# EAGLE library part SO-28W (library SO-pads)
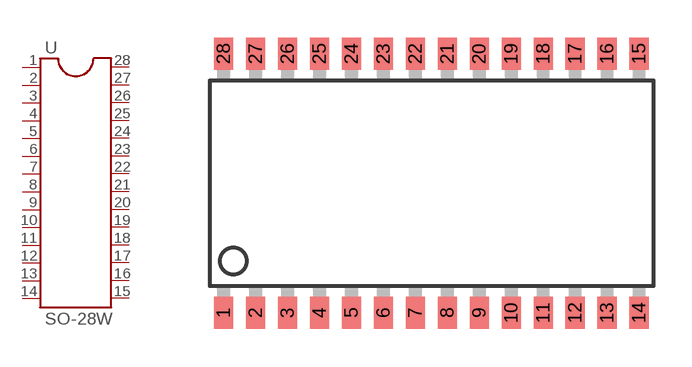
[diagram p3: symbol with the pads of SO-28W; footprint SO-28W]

Designator prefix -

## SO-28W  [SO-28W]
1  1  pas
2  2  pas
3  3  pas
4  4  pas
5  5  pas
6  6  pas
7  7  pas
8  8  pas
9  9  pas
10  10  pas
11  11  pas
12  12  pas
13  13  pas
14  14  pas
15  15  pas
16  16  pas
17  17  pas
18  18  pas
19  19  pas
20  20  pas
21  21  pas
22  22  pas
23  23  pas
24  24  pas
25  25  pas
26  26  pas
27  27  pas
28  28  pas

## Footprint SO-28W (pad centres in mm)
smd 0.762 x 1.27: 1 -7.62,-5.207; 2 -6.35,-5.207; 3 -5.08,-5.207; 4 -3.81,-5.207; 5 -2.54,-5.207; 6 -1.27,-5.207; 7 0,-5.207; 8 1.27,-5.207; 9 2.54,-5.207; 10 3.81,-5.207; 11 5.08,-5.207; 12 6.35,-5.207; 13 7.62,-5.207; 14 8.89,-5.207; 15 8.89,5.08; 16 7.62,5.08; 17 6.35,5.08; 18 5.08,5.08; 19 3.81,5.08; 20 2.54,5.08; 21 1.27,5.08; 22 0,5.08; 23 -1.27,5.08; 24 -2.54,5.08; 25 -3.81,5.08; 26 -5.08,5.08; 27 -6.35,5.08; 28 -7.62,5.08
